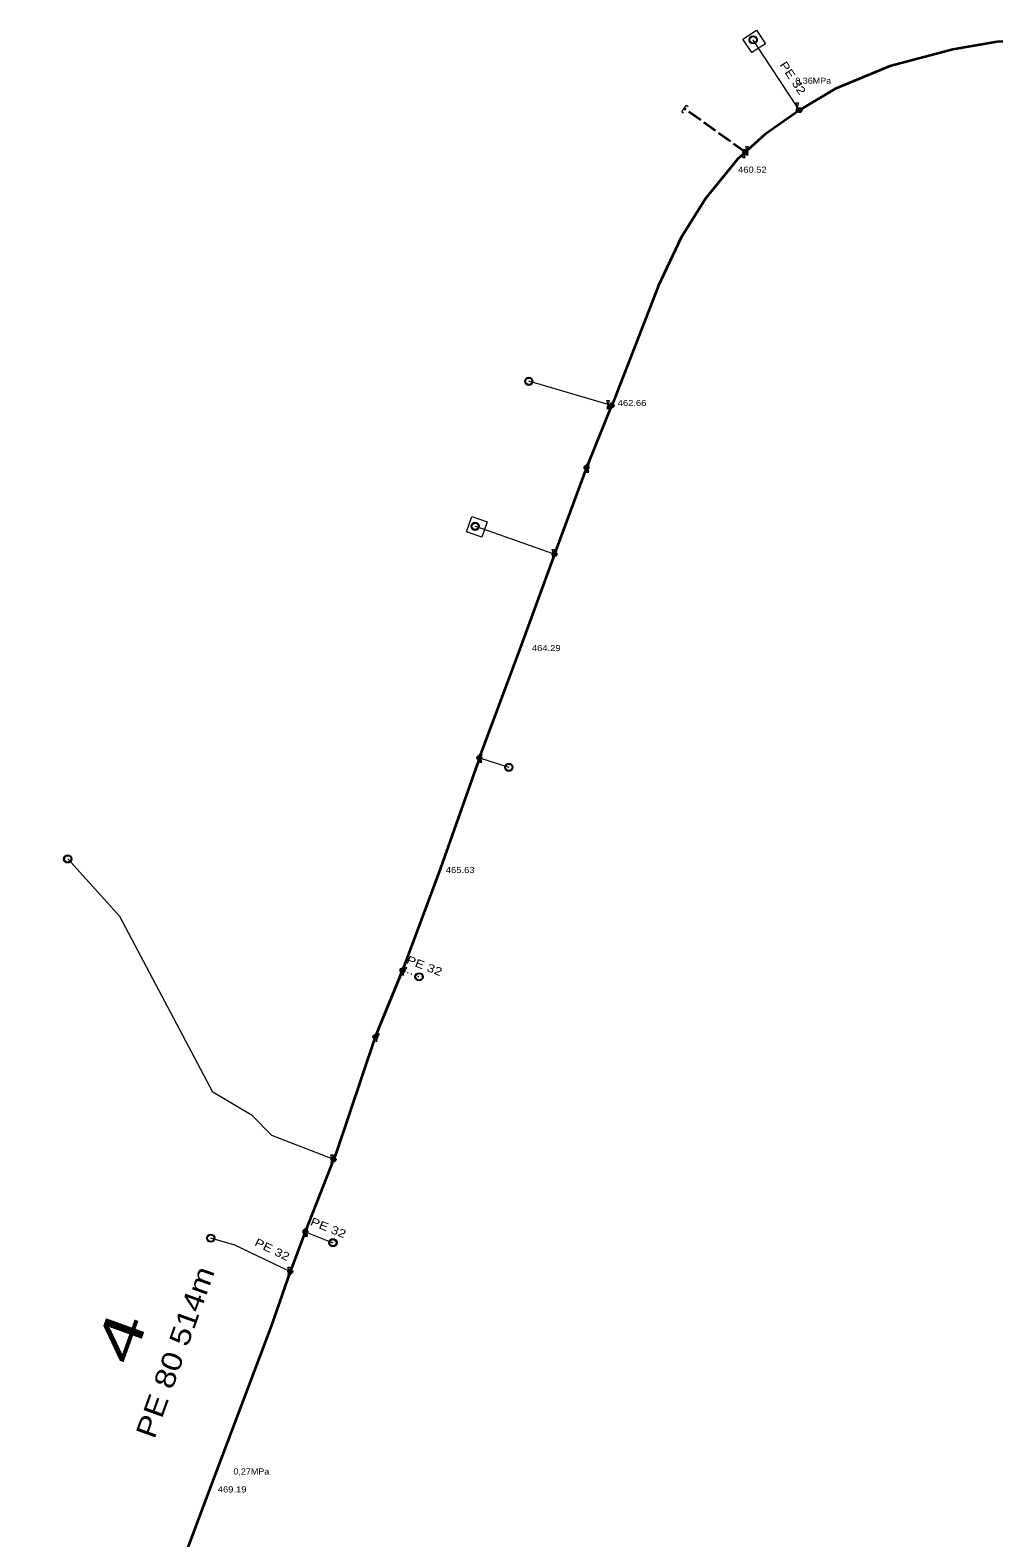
# Model space of a CAD drawing. Extents: x -687671 to -687504, y -1079137 to -1078766.
# Drawn here: x -687623.6 to -687503.8, y -1078951.3 to -1078765.8 of the extents above; entities that cross this region are included whole.
import ezdxf
from ezdxf.enums import TextEntityAlignment as Align

# ---------------------------------------------------------------- set-up
doc = ezdxf.new("R2010")
doc.units = 0
doc.header["$LTSCALE"] = 0.3
doc.linetypes.add('DOTTED', pattern=[1.5, 0.3, -1.2])
doc.linetypes.add('LONG_DASHED', pattern=[7.5, 6, -1.5])
for name, color, linetype, lineweight in [('10', 7, 'Continuous', 13), ('12', 7, 'Continuous', 13), ('35', 7, 'Continuous', 35), ('36', 7, 'LONG_DASHED', 35), ('50', 7, 'Continuous', 13), ('51', 7, 'LONG_DASHED', 13), ('63', 7, 'Continuous', 13)]:
    doc.layers.add(name, color=color, linetype=linetype, lineweight=lineweight)
for name, color, linetype in [('16', 7, 'Continuous'), ('17', 7, 'Continuous'), ('19', 7, 'Continuous'), ('2', 7, 'Continuous'), ('3', 7, 'Continuous')]:
    doc.layers.add(name, color=color, linetype=linetype)

msp = doc.modelspace()

# ---------------------------------------------------------------- linework, layer by layer
at = {"layer": '10'}
for p, q in [((-687543.315, -1078775.813), (-687542.733, -1078774.999)), ((-687542.733, -1078774.999), (-687542.53, -1078775.145)), ((-687543.315, -1078775.813), (-687543.111, -1078775.958))]:
    msp.add_line(p, q, dxfattribs=at)
for points in [[(-687533.024, -1078767.435), (-687534.695, -1078768.534), (-687535.794, -1078766.863), (-687534.123, -1078765.764)], [(-687535.541, -1078781.455), (-687535.841, -1078780.455), (-687535.541, -1078780.455), (-687535.841, -1078781.455)], [(-687535.137, -1078781.092), (-687535.437, -1078780.092), (-687535.137, -1078780.092), (-687535.437, -1078781.092)], [(-687567.271, -1078826.306), (-687567.932, -1078828.193), (-687569.819, -1078827.532), (-687569.158, -1078825.645)]]:
    msp.add_lwpolyline(points, close=True, dxfattribs=at)
at = {"layer": '12'}
for centre, radius in [((-687534.54, -1078766.95), 0.5), ((-687534.54, -1078766.95), 0.4), ((-687528.8226, -1078775.6059), 0.3), ((-687528.8226, -1078775.6059), 0.2), ((-687528.8226, -1078775.6059), 0.1), ((-687535.5006, -1078780.7839), 0.3), ((-687535.5006, -1078780.7839), 0.2), ((-687535.5006, -1078780.7839), 0.1), ((-687562.15, -1078808.99), 0.5), ((-687562.15, -1078808.99), 0.4), ((-687551.9614, -1078811.9616), 0.3), ((-687551.9614, -1078811.9616), 0.2), ((-687551.9614, -1078811.9616), 0.1), ((-687555.0553, -1078819.6091), 0.3), ((-687555.0553, -1078819.6091), 0.2), ((-687555.0553, -1078819.6091), 0.1), ((-687568.77, -1078826.84), 0.5), ((-687568.77, -1078826.84), 0.4), ((-687559.0001, -1078830.2633), 0.3), ((-687559.0001, -1078830.2633), 0.2), ((-687559.0001, -1078830.2633), 0.1), ((-687568.2447, -1078855.3358), 0.3), ((-687568.2447, -1078855.3358), 0.2), ((-687568.2447, -1078855.3358), 0.1), ((-687564.61, -1078856.5), 0.5), ((-687564.61, -1078856.5), 0.4), ((-687618.93, -1078867.78), 0.5), ((-687618.93, -1078867.78), 0.4), ((-687577.72, -1078881.49), 0.3), ((-687577.72, -1078881.49), 0.2), ((-687577.72, -1078881.49), 0.1), ((-687575.674, -1078882.287), 0.5), ((-687575.674, -1078882.287), 0.4), ((-687581.06, -1078889.68), 0.3), ((-687581.06, -1078889.68), 0.2), ((-687581.06, -1078889.68), 0.1), ((-687586.1937, -1078904.7799), 0.3), ((-687586.1937, -1078904.7799), 0.2), ((-687586.1937, -1078904.7799), 0.1), ((-687601.32, -1078914.46), 0.5), ((-687601.32, -1078914.46), 0.4), ((-687589.6807, -1078913.6673), 0.3), ((-687589.6807, -1078913.6673), 0.2), ((-687589.6807, -1078913.6673), 0.1), ((-687586.27, -1078915.02), 0.5), ((-687586.27, -1078915.02), 0.4), ((-687591.5294, -1078918.5763), 0.3), ((-687591.5294, -1078918.5763), 0.2), ((-687591.5294, -1078918.5763), 0.1)]:
    msp.add_circle(centre, radius, dxfattribs=at)
at = {"layer": '35'}
msp.add_line((-687577.72, -1078881.49), (-687581.06, -1078889.68), dxfattribs=at)
for points in [[(-687503.795, -1078767.147), (-687504.5, -1078767.19), (-687509.96, -1078768.14), (-687517.69, -1078770.2), (-687524.43, -1078773), (-687528.63, -1078775.47), (-687528.823, -1078775.606)], [(-687528.823, -1078775.606), (-687533.08, -1078778.61), (-687535.287, -1078780.592)], [(-687535.691, -1078780.955), (-687536.42, -1078781.61), (-687540.37, -1078786.46), (-687543.39, -1078791.27), (-687546.25, -1078797.28), (-687546.32, -1078797.52), (-687551.79, -1078811.54), (-687551.961, -1078811.962)], [(-687535.287, -1078780.592), (-687535.501, -1078780.784), (-687535.691, -1078780.955)], [(-687551.961, -1078811.962), (-687554.9, -1078819.19), (-687555.055, -1078819.609)], [(-687555.055, -1078819.609), (-687558.74, -1078829.55), (-687559, -1078830.263)], [(-687559, -1078830.263), (-687563.13, -1078841.59), (-687568.13, -1078855.01), (-687568.245, -1078855.336)], [(-687568.245, -1078855.336), (-687573.02, -1078868.9), (-687577.72, -1078881.49)], [(-687581.06, -1078889.68), (-687585.97, -1078904.21), (-687586.194, -1078904.78)], [(-687586.194, -1078904.78), (-687589.64, -1078913.56), (-687589.681, -1078913.667)], [(-687589.681, -1078913.667), (-687591.38, -1078918.15), (-687591.529, -1078918.576)], [(-687591.529, -1078918.576), (-687593.89, -1078925.31), (-687601.42, -1078945.26), (-687606.74, -1078959.45), (-687612.17, -1078974.38), (-687617.62, -1078988.97), (-687623.555, -1079004.943)]]:
    msp.add_lwpolyline(points, dxfattribs=at)
at = {"layer": '36'}
msp.add_line((-687535.501, -1078780.784), (-687543.024, -1078775.406), dxfattribs=at)
at = {"layer": '50'}
for p, q in [((-687534.409, -1078767.149), (-687534.54, -1078766.95)), ((-687529.12, -1078775.19), (-687534.409, -1078767.149)), ((-687529.12, -1078775.19), (-687528.823, -1078775.606)), ((-687552.4, -1078811.84), (-687562.15, -1078808.99)), ((-687552.4, -1078811.84), (-687551.961, -1078811.962)), ((-687559.15, -1078830.21), (-687559, -1078830.263)), ((-687568.245, -1078855.336), (-687568.1, -1078855.38)), ((-687568.1, -1078855.38), (-687564.61, -1078856.5)), ((-687586.194, -1078904.78), (-687586.39, -1078904.71)), ((-687589.56, -1078913.71), (-687589.681, -1078913.667)), ((-687589.56, -1078913.71), (-687586.27, -1078915.02)), ((-687591.529, -1078918.576), (-687591.67, -1078918.52))]:
    msp.add_line(p, q, dxfattribs=at)
for points in [[(-687559.15, -1078830.21), (-687568.545, -1078826.919), (-687568.77, -1078826.84)], [(-687586.39, -1078904.71), (-687593.81, -1078901.82), (-687596.2, -1078899.36), (-687601.08, -1078896.5), (-687612.51, -1078874.85), (-687618.93, -1078867.78)], [(-687591.67, -1078918.52), (-687598.34, -1078915.31), (-687601.32, -1078914.46)]]:
    msp.add_lwpolyline(points, dxfattribs=at)
at = {"layer": '51'}
for p, q in [((-687555.055, -1078819.609), (-687554.9, -1078819.67)), ((-687577.72, -1078881.49), (-687577.529, -1078881.575)), ((-687581.06, -1078889.68), (-687580.866, -1078889.755))]:
    msp.add_line(p, q, dxfattribs=at)
at = {"layer": '51', "linetype": 'DOTTED'}
msp.add_line((-687577.529, -1078881.575), (-687575.674, -1078882.287), dxfattribs=at)
at = {"layer": '63'}
for points in [[(-687528.97, -1078775.69), (-687529.27, -1078774.69), (-687528.97, -1078774.69), (-687529.27, -1078775.69)], [(-687552.25, -1078812.34), (-687552.55, -1078811.34), (-687552.25, -1078811.34), (-687552.55, -1078812.34)], [(-687554.75, -1078820.17), (-687555.05, -1078819.17), (-687554.75, -1078819.17), (-687555.05, -1078820.17)], [(-687559, -1078830.71), (-687559.3, -1078829.71), (-687559, -1078829.71), (-687559.3, -1078830.71)], [(-687567.95, -1078855.88), (-687568.25, -1078854.88), (-687567.95, -1078854.88), (-687568.25, -1078855.88)], [(-687577.569, -1078882.096), (-687577.488, -1078881.055), (-687577.208, -1078881.163), (-687577.849, -1078881.988)], [(-687580.82, -1078889.235), (-687580.912, -1078890.275), (-687581.191, -1078890.163), (-687580.541, -1078889.346)], [(-687586.24, -1078905.21), (-687586.54, -1078904.21), (-687586.24, -1078904.21), (-687586.54, -1078905.21)], [(-687589.41, -1078914.21), (-687589.71, -1078913.21), (-687589.41, -1078913.21), (-687589.71, -1078914.21)], [(-687591.52, -1078919.02), (-687591.82, -1078918.02), (-687591.52, -1078918.02), (-687591.82, -1078919.02)]]:
    msp.add_lwpolyline(points, close=True, dxfattribs=at)

# ---------------------------------------------------------------- texts
at = {"layer": '16', "width": 1.6}
msp.add_text('4', height=5, rotation=70.187, dxfattribs=at).set_placement((-687610.0608, -1078927.5409), align=Align.CENTER)
at = {"layer": '17', "width": 1.2}
msp.add_text('PE 80 514m', height=2.5, rotation=70.187, dxfattribs=at).set_placement((-687604.5211, -1078928.9057), align=Align.CENTER)
at = {"layer": '19', "width": 1.25}
for rotation, p in [(303.336, (-687530.0712, -1078771.9237)), (339.002, (-687575.1902, -1078881.4013)), (338.289, (-687587.0255, -1078913.6427)), (334.3, (-687593.9633, -1078916.3063))]:
    msp.add_text('PE 32', height=1, rotation=rotation, dxfattribs=at).set_placement(p, align=Align.CENTER)
at = {"layer": '2', "width": 1.1}
for s, p in [('0,36MPa', (-687529.346, -1078772.358)), ('0,27MPa', (-687598.525, -1078943.554))]:
    msp.add_text(s, height=0.75, dxfattribs=at).set_placement(p)
at = {"layer": '3', "width": 1.15}
for s, p in [('460.52', (-687534.632, -1078783.311)), ('462.66', (-687549.449, -1078812.033)), ('464.29', (-687560.011, -1078842.198)), ('465.63', (-687570.611, -1078869.514)), ('469.19', (-687598.687, -1078945.764))]:
    msp.add_text(s, height=0.75, dxfattribs=at).set_placement(p, align=Align.CENTER)

doc.saveas('drawing.dxf')
